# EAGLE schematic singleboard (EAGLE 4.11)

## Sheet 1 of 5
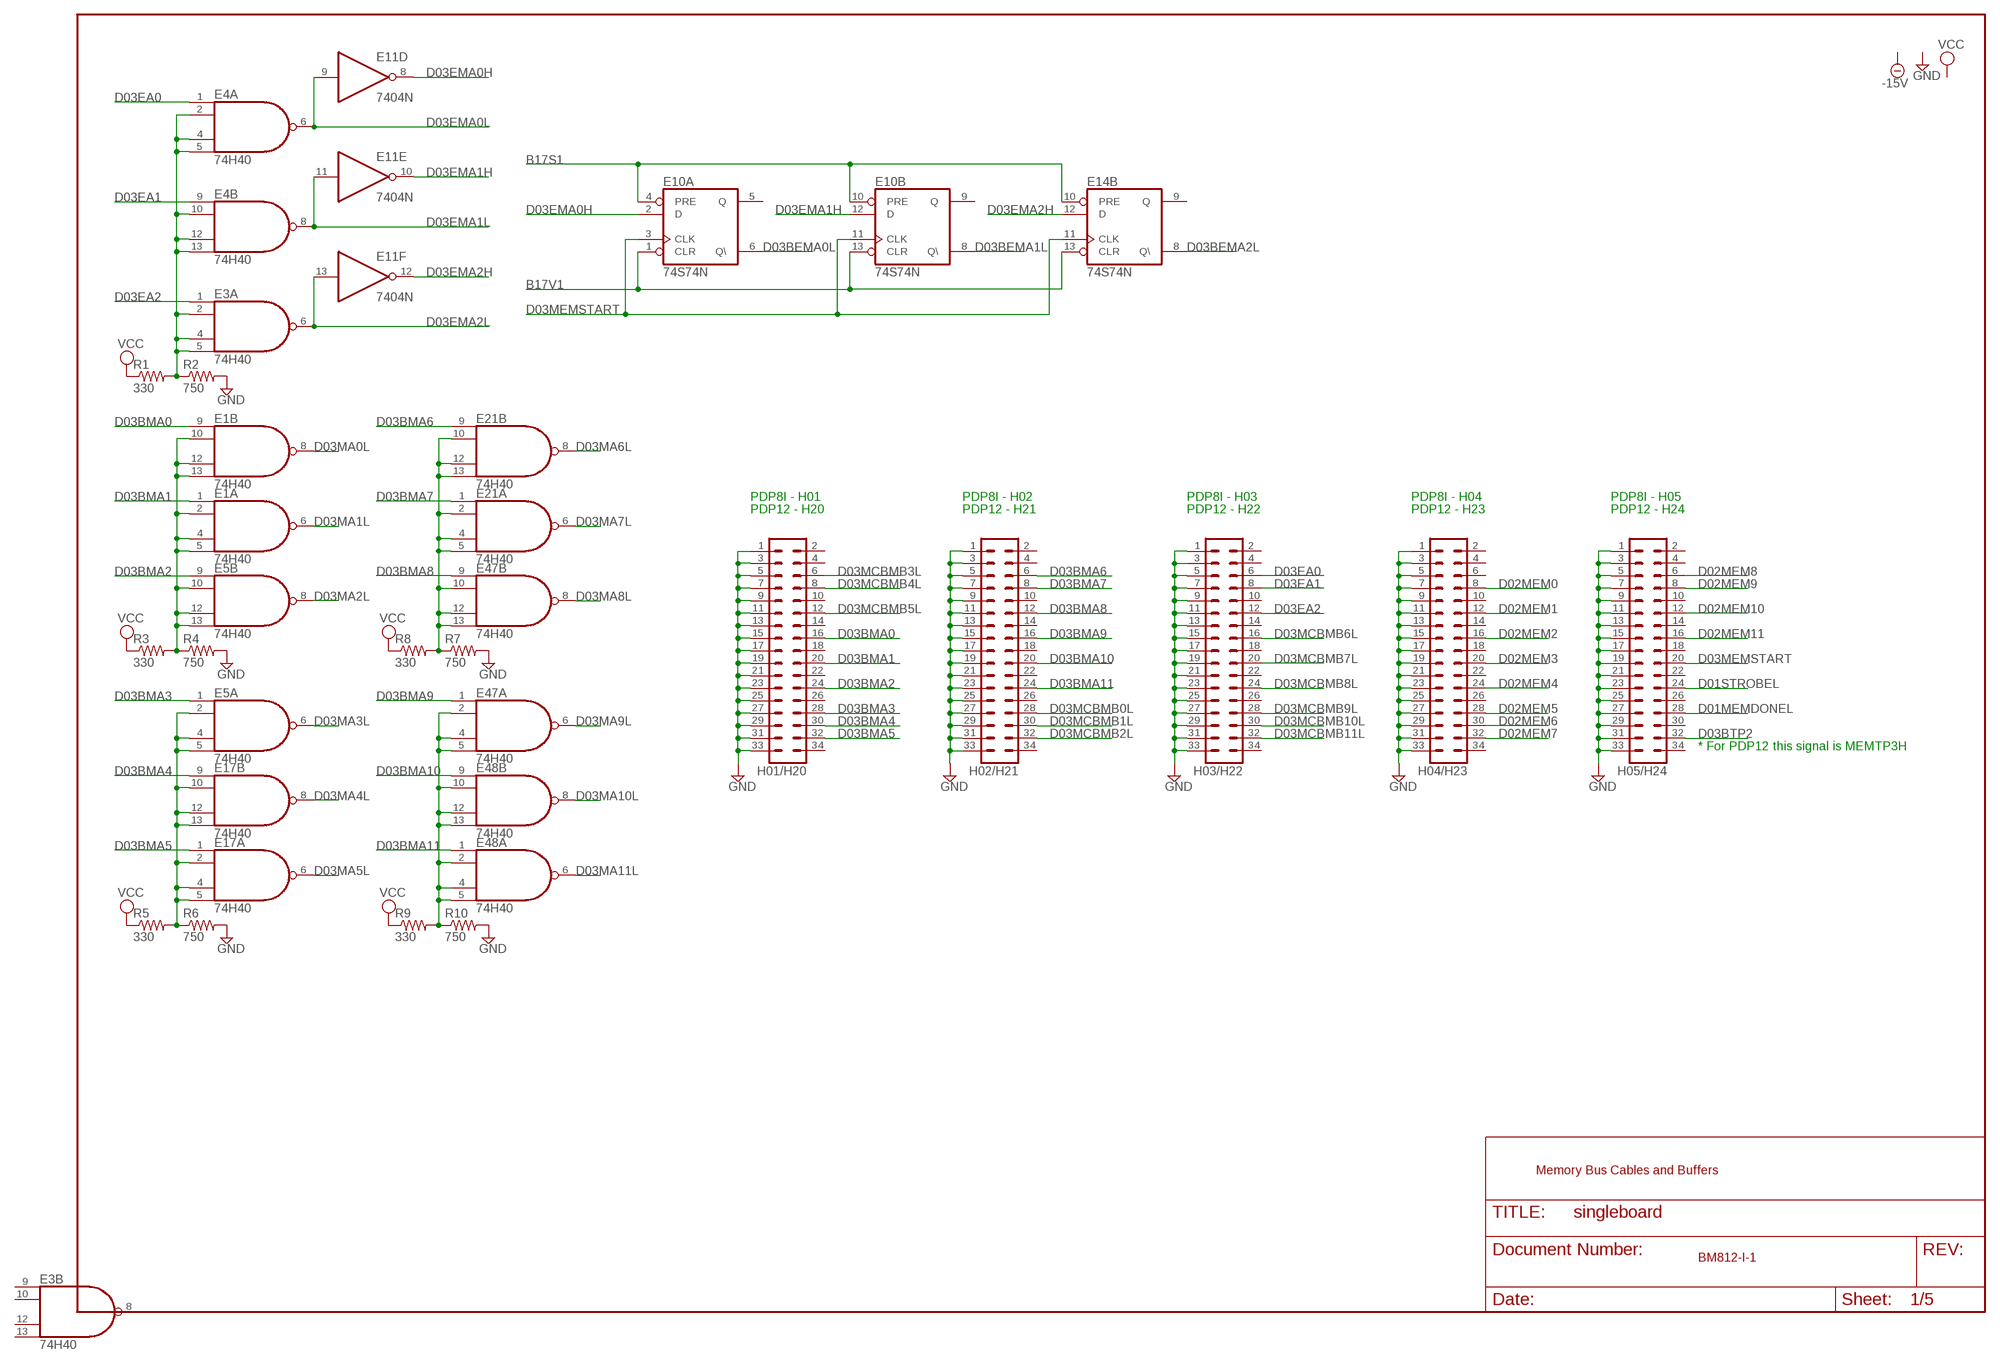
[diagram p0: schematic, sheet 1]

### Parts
E1  74H40  74S20N  [DIL14]
E3  74H40  74S20N  [DIL14]
E4  74H40  74S20N  [DIL14]
E5  74H40  74S20N  [DIL14]
E10  74S74N  [DIL14]
E11  7404N  [DIL14]
E14  74S74N  [DIL14]
E17  74H40  74S20N  [DIL14]
E21  74H40  74S20N  [DIL14]
E47  74H40  74S20N  [DIL14]
E48  74H40  74S20N  [DIL14]
H01/H20  MA17-2  [MA17-2]
H02/H21  MA17-2  [MA17-2]
H03/H22  MA17-2  [MA17-2]
H04/H23  MA17-2  [MA17-2]
H05/H24  MA17-2  [MA17-2]
R1  330  R-US_0207/10  [0207/10]
R2  750  R-US_0207/10  [0207/10]
R3  330  R-US_0207/10  [0207/10]
R4  750  R-US_0207/10  [0207/10]
R5  330  R-US_0207/10  [0207/10]
R6  750  R-US_0207/10  [0207/10]
R7  750  R-US_0207/10  [0207/10]
R8  330  R-US_0207/10  [0207/10]
R9  330  R-US_0207/10  [0207/10]
R10  750  R-US_0207/10  [0207/10]

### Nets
B17S1: E10.4(A:PRE) E10.10(B:PRE) E14.10(B:PRE) ; also sheet 3,4
B17V1: E10.1(A:CLR) E10.13(B:CLR) E14.13(B:CLR) ; also sheet 3,4
D01MEMDONEL: H05/H24.28 ; also sheet 4
D01STROBEL: H05/H24.24 ; also sheet 4
D02MEM0: H04/H23.8 ; also sheet 3
D02MEM1: H04/H23.12 ; also sheet 3
D02MEM2: H04/H23.16 ; also sheet 3
D02MEM3: H04/H23.20 ; also sheet 3
D02MEM4: H04/H23.24 ; also sheet 3
D02MEM5: H04/H23.28 ; also sheet 3
D02MEM6: H04/H23.30 ; also sheet 3
D02MEM7: H04/H23.32 ; also sheet 3
D02MEM8: H05/H24.6 ; also sheet 3
D02MEM9: H05/H24.8 ; also sheet 3
D02MEM10: H05/H24.12 ; also sheet 3
D02MEM11: H05/H24.16 ; also sheet 3
D03BEMA0L: E10.6(A:Q\) ; also sheet 5
D03BEMA1L: E10.8(B:Q\) ; also sheet 5
D03BEMA2L: E14.8(B:Q\) ; also sheet 5
D03BMA0: E1.9(B:I0) H01/H20.16
D03BMA1: E1.1(A:I0) H01/H20.20
D03BMA2: E5.9(B:I0) H01/H20.24
D03BMA3: E5.1(A:I0) H01/H20.28
D03BMA4: E17.9(B:I0) H01/H20.30
D03BMA5: E17.1(A:I0) H01/H20.32
D03BMA6: E21.9(B:I0) H02/H21.6
D03BMA7: E21.1(A:I0) H02/H21.8
D03BMA8: E47.9(B:I0) H02/H21.12
D03BMA9: E47.1(A:I0) H02/H21.16
D03BMA10: E48.9(B:I0) H02/H21.20
D03BMA11: E48.1(A:I0) H02/H21.24
D03BTP2: H05/H24.32 ; also sheet 4
D03EA0: E4.1(A:I0) H03/H22.6
D03EA1: E4.9(B:I0) H03/H22.8
D03EA2: E3.1(A:I0) H03/H22.12
D03EMA0H: E10.2(A:D) E11.8(D:O) ; also sheet 4
D03EMA0L: E4.6(A:O) E11.9(D:I) ; also sheet 4
D03EMA1H: E10.12(B:D) E11.10(E:O) ; also sheet 4
D03EMA1L: E4.8(B:O) E11.11(E:I) ; also sheet 4
D03EMA2H: E11.12(F:O) E14.12(B:D) ; also sheet 4
D03EMA2L: E3.6(A:O) E11.13(F:I) ; also sheet 4
D03MA0L: E1.8(B:O) ; also sheet 5
D03MA1L: E1.6(A:O) ; also sheet 5
D03MA2L: E5.8(B:O) ; also sheet 5
D03MA3L: E5.6(A:O) ; also sheet 5
D03MA4L: E17.8(B:O) ; also sheet 5
D03MA5L: E17.6(A:O) ; also sheet 5
D03MA6L: E21.8(B:O) ; also sheet 5
D03MA7L: E21.6(A:O) ; also sheet 5
D03MA8L: E47.8(B:O) ; also sheet 5
D03MA9L: E47.6(A:O) ; also sheet 5
D03MA10L: E48.8(B:O) ; also sheet 5
D03MA11L: E48.6(A:O) ; also sheet 5
D03MCBMB0L: H02/H21.28 ; also sheet 2
D03MCBMB1L: H02/H21.30 ; also sheet 2
D03MCBMB2L: H02/H21.32 ; also sheet 2
D03MCBMB3L: H01/H20.6 ; also sheet 2
D03MCBMB4L: H01/H20.8 ; also sheet 2
D03MCBMB5L: H01/H20.12 ; also sheet 2
D03MCBMB6L: H03/H22.16 ; also sheet 2
D03MCBMB7L: H03/H22.20 ; also sheet 2
D03MCBMB8L: H03/H22.24 ; also sheet 2
D03MCBMB9L: H03/H22.28 ; also sheet 2
D03MCBMB10L: H03/H22.30 ; also sheet 2
D03MCBMB11L: H03/H22.32 ; also sheet 2
D03MEMSTART: E10.3(A:CLK) E10.11(B:CLK) E14.11(B:CLK) H05/H24.20 ; also sheet 4
GND [Power]: H01/H20.1 H01/H20.3 H01/H20.5 H01/H20.7 H01/H20.9 H01/H20.11 H01/H20.13 H01/H20.15 H01/H20.17 H01/H20.19 H01/H20.21 H01/H20.23 H01/H20.25 H01/H20.27 H01/H20.29 H01/H20.31 H01/H20.33 H02/H21.1 H02/H21.3 H02/H21.5 H02/H21.7 H02/H21.9 H02/H21.11 H02/H21.13 H02/H21.15 H02/H21.17 H02/H21.19 H02/H21.21 H02/H21.23 H02/H21.25 H02/H21.27 H02/H21.29 H02/H21.31 H02/H21.33 H03/H22.1 H03/H22.3 H03/H22.5 H03/H22.7 H03/H22.9 H03/H22.11 H03/H22.13 H03/H22.15 H03/H22.17 H03/H22.19 H03/H22.21 H03/H22.23 H03/H22.25 H03/H22.27 H03/H22.29 H03/H22.31 H03/H22.33 H04/H23.1 H04/H23.3 H04/H23.5 H04/H23.7 H04/H23.9 H04/H23.11 H04/H23.13 H04/H23.15 H04/H23.17 H04/H23.19 H04/H23.21 H04/H23.23 H04/H23.25 H04/H23.27 H04/H23.29 H04/H23.31 H04/H23.33 H05/H24.1 H05/H24.3 H05/H24.5 H05/H24.7 H05/H24.9 H05/H24.11 H05/H24.13 H05/H24.15 H05/H24.17 H05/H24.19 H05/H24.21 H05/H24.23 H05/H24.25 H05/H24.27 H05/H24.29 H05/H24.31 H05/H24.33 R2.2 R4.2 R6.2 R7.2 R10.2 ; also sheet 2,4,5
N$1: E3.2(A:I1) E3.4(A:I2) E3.5(A:I3) E4.2(A:I1) E4.4(A:I2) E4.5(A:I3) E4.10(B:I1) E4.12(B:I2) E4.13(B:I3) R1.2 R2.1
N$2: E1.2(A:I1) E1.4(A:I2) E1.5(A:I3) E1.10(B:I1) E1.12(B:I2) E1.13(B:I3) E5.10(B:I1) E5.12(B:I2) E5.13(B:I3) R3.2 R4.1
N$4: E5.2(A:I1) E5.4(A:I2) E5.5(A:I3) E17.2(A:I1) E17.4(A:I2) E17.5(A:I3) E17.10(B:I1) E17.12(B:I2) E17.13(B:I3) R5.2 R6.1
N$6: E21.2(A:I1) E21.4(A:I2) E21.5(A:I3) E21.10(B:I1) E21.12(B:I2) E21.13(B:I3) E47.10(B:I1) E47.12(B:I2) E47.13(B:I3) R7.1 R8.2
N$36: E47.2(A:I1) E47.4(A:I2) E47.5(A:I3) E48.2(A:I1) E48.4(A:I2) E48.5(A:I3) E48.10(B:I1) E48.12(B:I2) E48.13(B:I3) R9.2 R10.1
VCC [Power]: R1.1 R3.1 R5.1 R8.1 R9.1 ; also sheet 2,4,5
Unconnected: E10.5(A:Q) E10.9(B:Q) H01/H20.2 H01/H20.4 H01/H20.10 H01/H20.14 H01/H20.18 H01/H20.22 H01/H20.26 H01/H20.34 H02/H21.2 H02/H21.4 H02/H21.10 H02/H21.14 H02/H21.18 H02/H21.22 H02/H21.26 H02/H21.34 H03/H22.2 H03/H22.4 H03/H22.10 H03/H22.14 H03/H22.18 H03/H22.22 H03/H22.26 H03/H22.34 H04/H23.2 H04/H23.4 H04/H23.6 H04/H23.10 H04/H23.14 H04/H23.18 H04/H23.22 H04/H23.26 H04/H23.34 H05/H24.2 H05/H24.4 H05/H24.10 H05/H24.14 H05/H24.18 H05/H24.22 H05/H24.26 H05/H24.30 H05/H24.34

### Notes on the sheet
- PDP8I - H01 | PDP8I - H02 | PDP8I - H03 | PDP8I - H04 | PDP8I - H05
- PDP12 - H20 | PDP12 - H21 | PDP12 - H22 | PDP12 - H23 | PDP12 - H24
- * For PDP12 this signal is MEMTP3H
- Memory Bus Cables and Buffers
- BM812-I-1

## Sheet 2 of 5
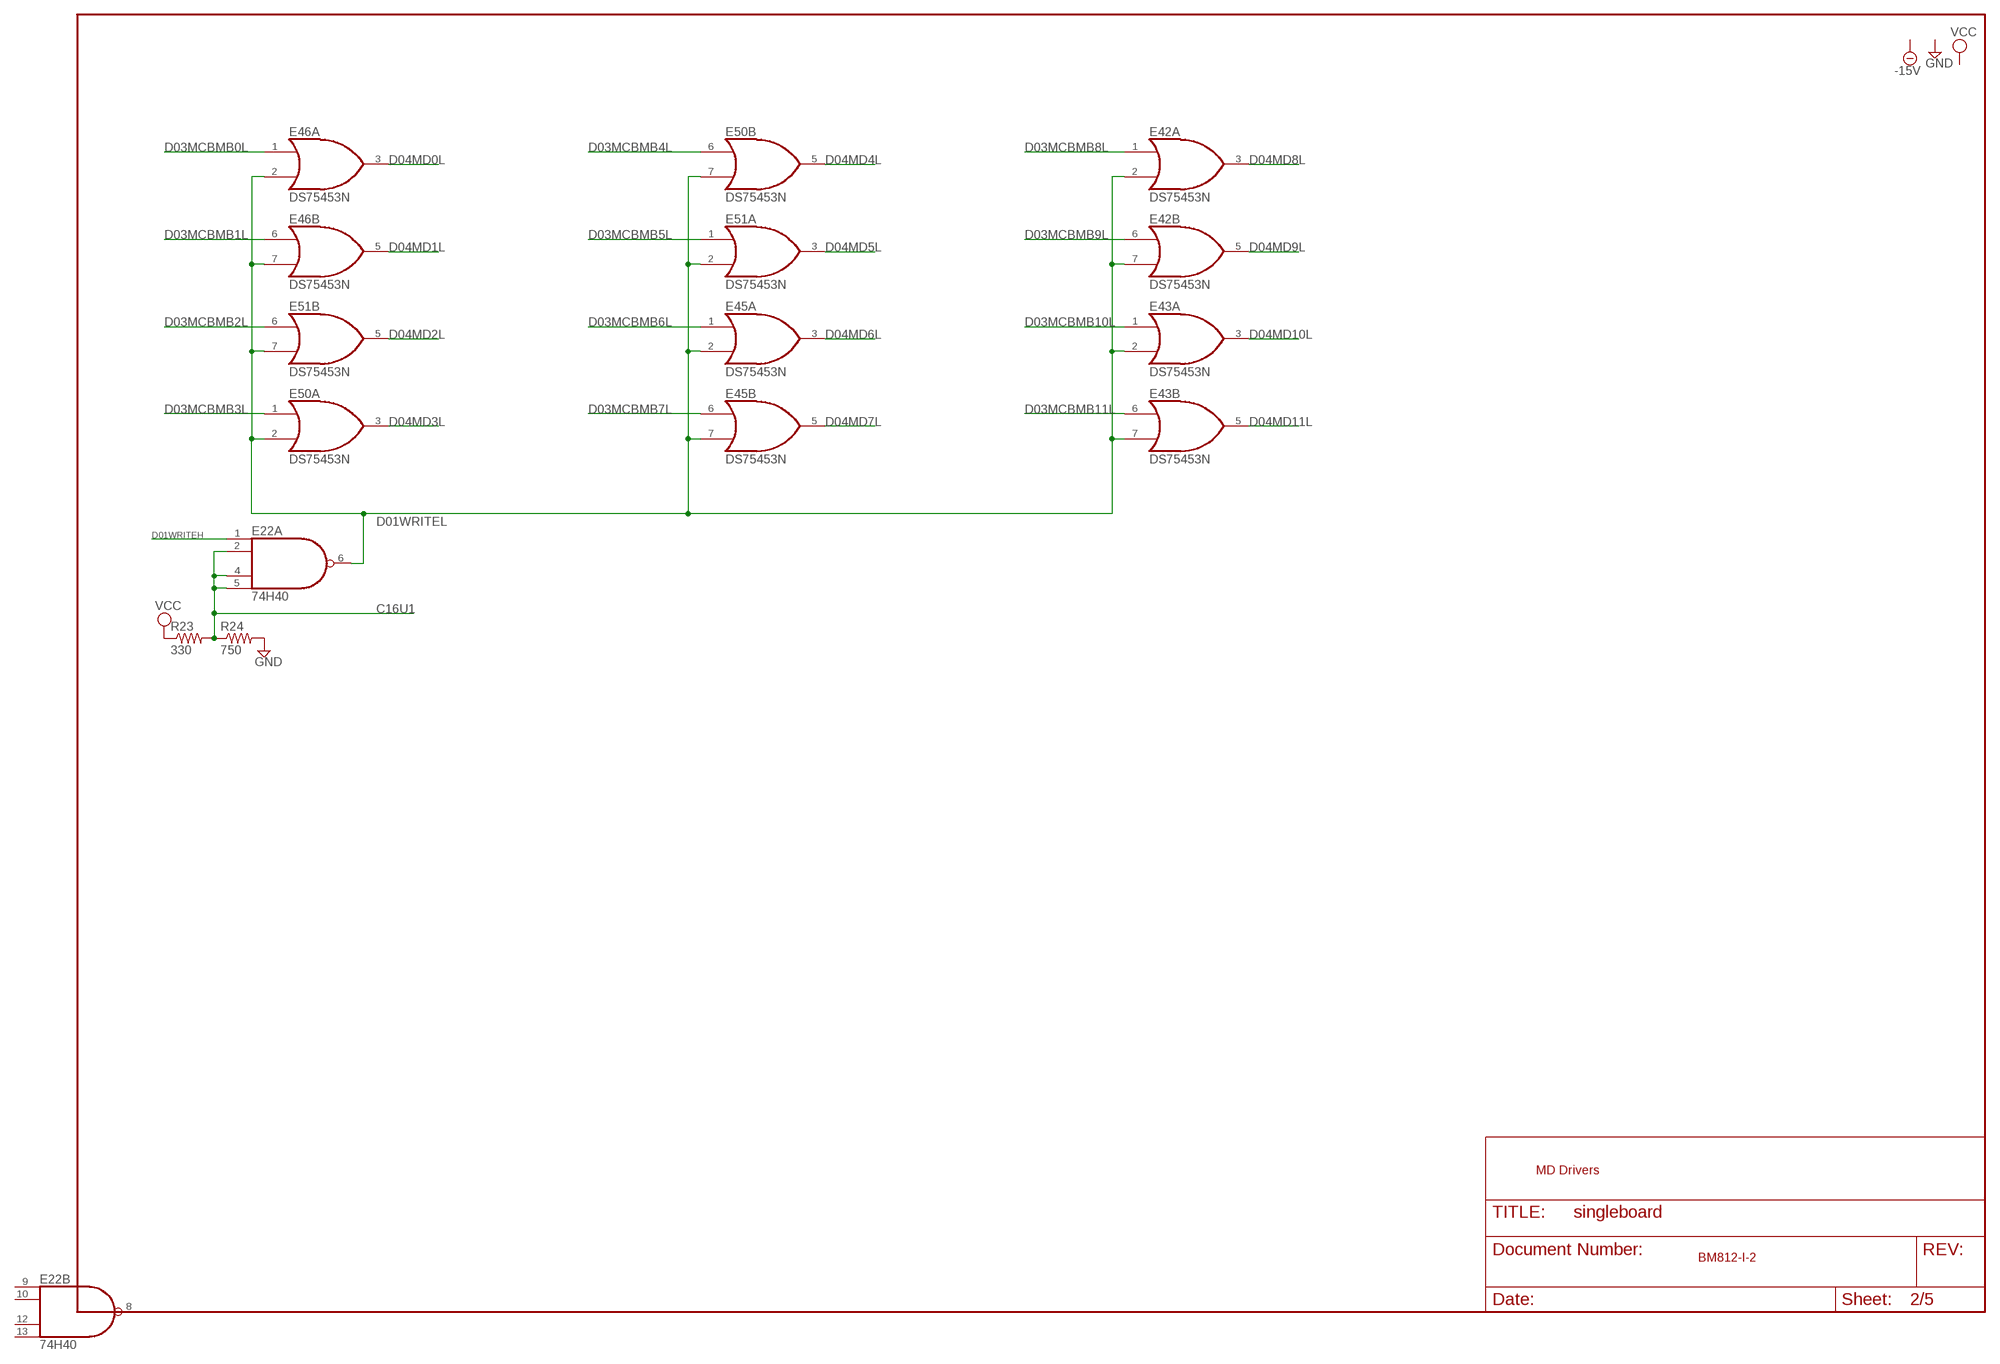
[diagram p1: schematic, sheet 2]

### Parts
E22  74H40  74S20N  [DIL14]
E42  DS75453N  [DIL08]
E43  DS75453N  [DIL08]
E45  DS75453N  [DIL08]
E46  DS75453N  [DIL08]
E50  DS75453N  [DIL08]
E51  DS75453N  [DIL08]
R23  330  R-US_0207/10  [0207/10]
R24  750  R-US_0207/10  [0207/10]

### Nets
C16U1: E22.2(A:I1) E22.4(A:I2) E22.5(A:I3) R23.2 R24.1 ; also sheet 3
D01WRITEH: E22.1(A:I0) ; also sheet 4
D01WRITEL: E22.6(A:O) E42.2(A:I1) E42.7(B:I1) E43.2(A:I1) E43.7(B:I1) E45.2(A:I1) E45.7(B:I1) E46.2(A:I1) E46.7(B:I1) E50.2(A:I1) E50.7(B:I1) E51.2(A:I1) E51.7(B:I1)
D03MCBMB0L: E46.1(A:I0) ; also sheet 1
D03MCBMB1L: E46.6(B:I0) ; also sheet 1
D03MCBMB2L: E51.6(B:I0) ; also sheet 1
D03MCBMB3L: E50.1(A:I0) ; also sheet 1
D03MCBMB4L: E50.6(B:I0) ; also sheet 1
D03MCBMB5L: E51.1(A:I0) ; also sheet 1
D03MCBMB6L: E45.1(A:I0) ; also sheet 1
D03MCBMB7L: E45.6(B:I0) ; also sheet 1
D03MCBMB8L: E42.1(A:I0) ; also sheet 1
D03MCBMB9L: E42.6(B:I0) ; also sheet 1
D03MCBMB10L: E43.1(A:I0) ; also sheet 1
D03MCBMB11L: E43.6(B:I0) ; also sheet 1
D04MD0L: E46.3(A:O) ; also sheet 3,5
D04MD1L: E46.5(B:O) ; also sheet 3,5
D04MD2L: E51.5(B:O) ; also sheet 3,5
D04MD3L: E50.3(A:O) ; also sheet 3,5
D04MD4L: E50.5(B:O) ; also sheet 3,5
D04MD5L: E51.3(A:O) ; also sheet 3,5
D04MD6L: E45.3(A:O) ; also sheet 3,5
D04MD7L: E45.5(B:O) ; also sheet 3,5
D04MD8L: E42.3(A:O) ; also sheet 3,5
D04MD9L: E42.5(B:O) ; also sheet 3,5
D04MD10L: E43.3(A:O) ; also sheet 3,5
D04MD11L: E43.5(B:O) ; also sheet 3,5
GND [Power]: R24.2 ; also sheet 1,4,5
VCC [Power]: R23.1 ; also sheet 1,4,5

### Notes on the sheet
- MD Drivers
- BM812-I-2

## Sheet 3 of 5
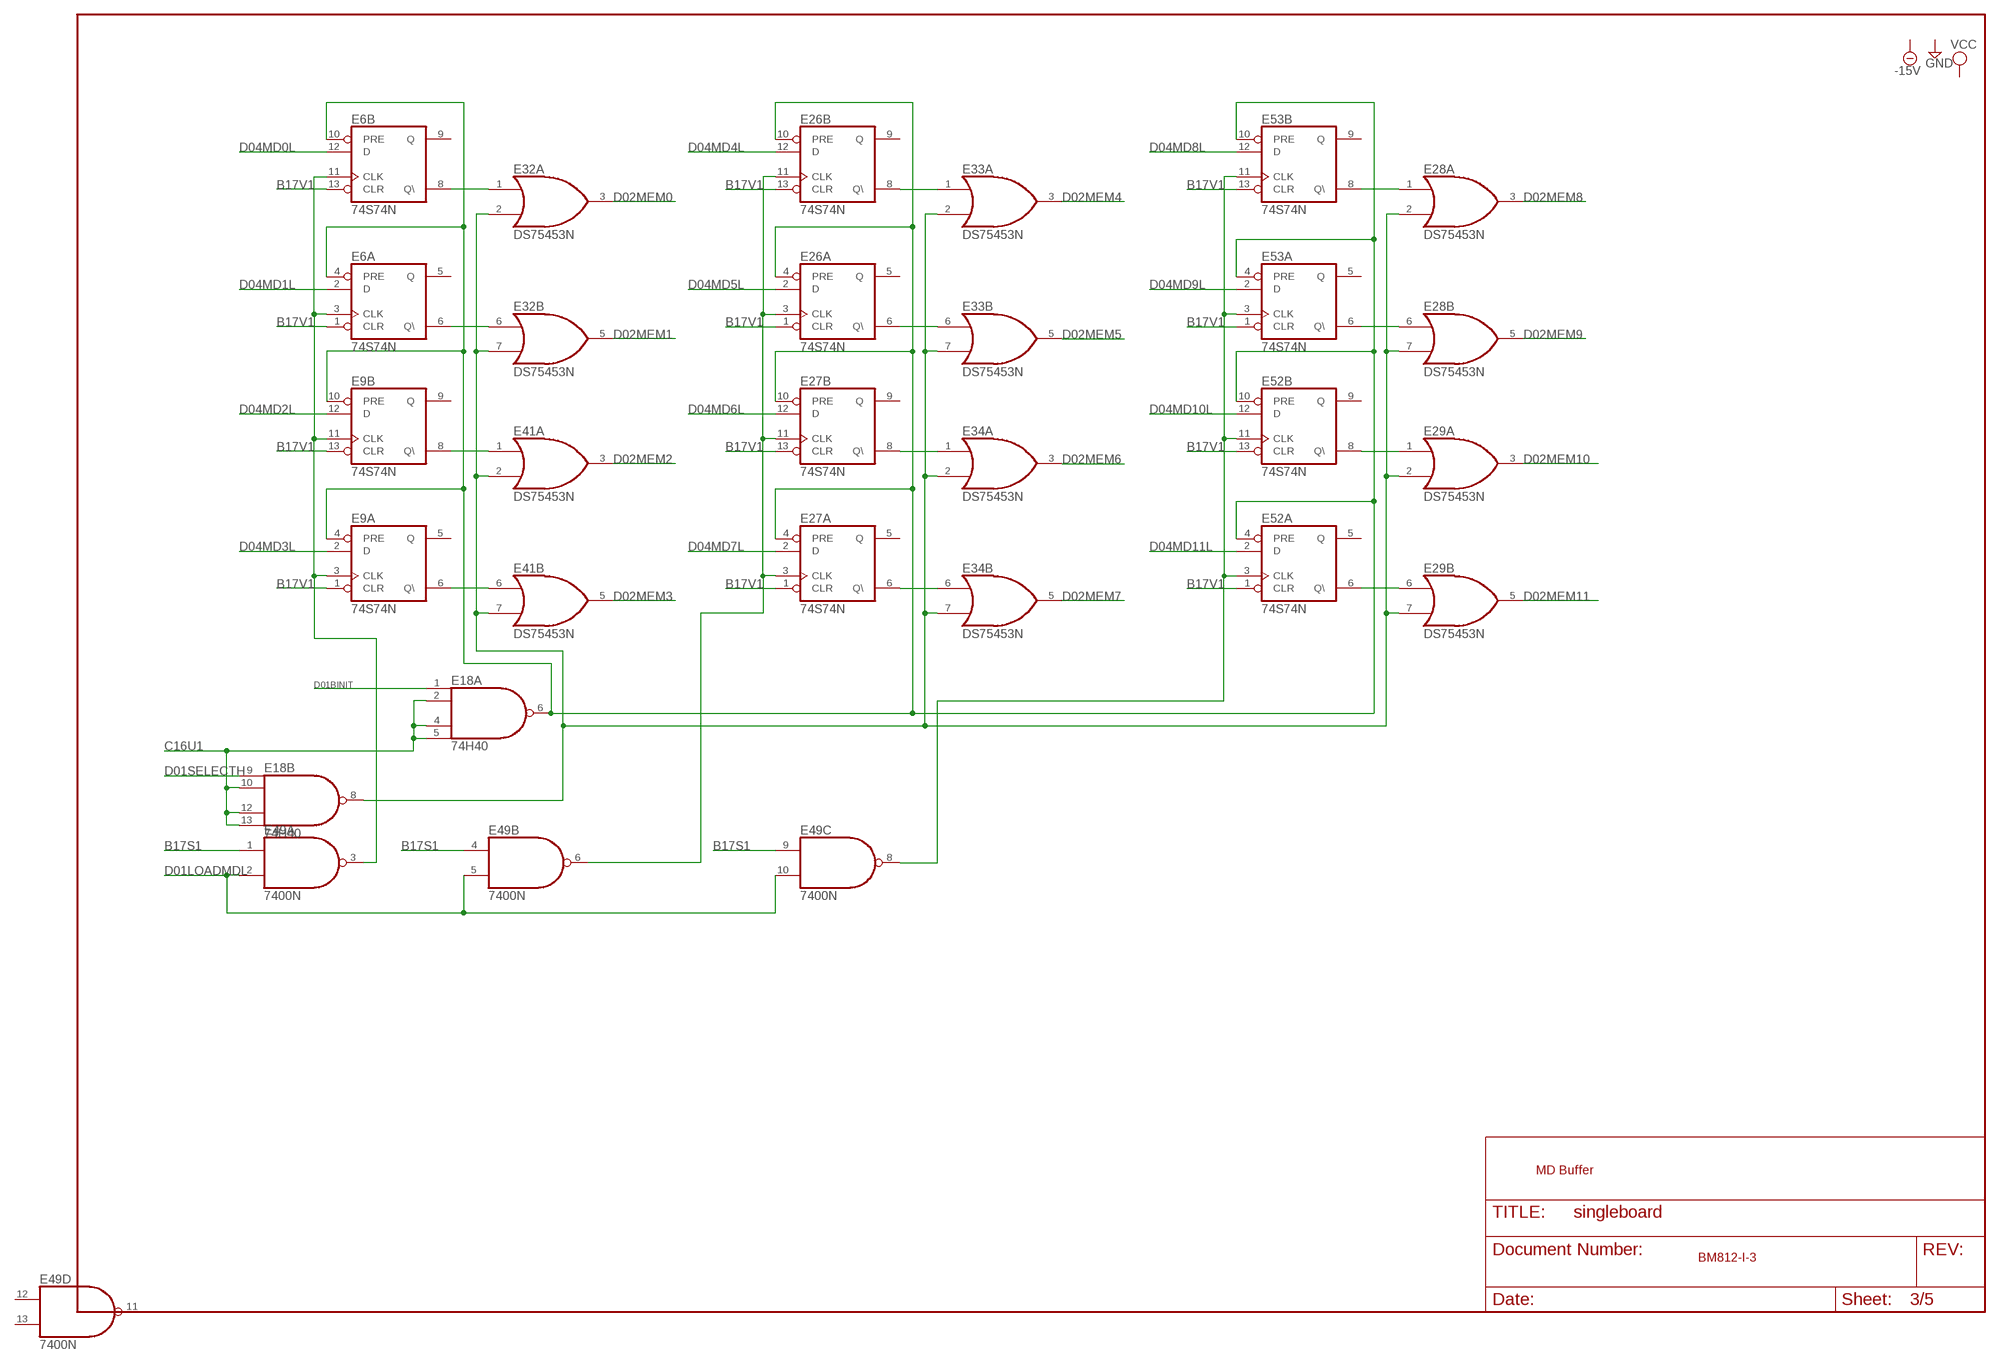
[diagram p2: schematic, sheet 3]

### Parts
E6  74S74N  [DIL14]
E9  74S74N  [DIL14]
E18  74H40  74S20N  [DIL14]
E26  74S74N  [DIL14]
E27  74S74N  [DIL14]
E28  DS75453N  [DIL08]
E29  DS75453N  [DIL08]
E32  DS75453N  [DIL08]
E33  DS75453N  [DIL08]
E34  DS75453N  [DIL08]
E41  DS75453N  [DIL08]
E49  7400N  [DIL14]
E52  74S74N  [DIL14]
E53  74S74N  [DIL14]

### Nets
B17S1: E49.1(A:I0) E49.4(B:I0) E49.9(C:I0) ; also sheet 1,4
B17V1: E6.1(A:CLR) E6.13(B:CLR) E9.1(A:CLR) E9.13(B:CLR) E26.1(A:CLR) E26.13(B:CLR) E27.1(A:CLR) E27.13(B:CLR) E52.1(A:CLR) E52.13(B:CLR) E53.1(A:CLR) E53.13(B:CLR) ; also sheet 1,4
C16U1: E18.2(A:I1) E18.4(A:I2) E18.5(A:I3) E18.10(B:I1) E18.12(B:I2) E18.13(B:I3) ; also sheet 2
D01BINIT: E18.1(A:I0) ; also sheet 4
D01LOADMDL: E49.2(A:I1) E49.5(B:I1) E49.10(C:I1) ; also sheet 4
D01SELECTH: E18.9(B:I0) ; also sheet 4
D02MEM0: E32.3(A:O) ; also sheet 1
D02MEM1: E32.5(B:O) ; also sheet 1
D02MEM2: E41.3(A:O) ; also sheet 1
D02MEM3: E41.5(B:O) ; also sheet 1
D02MEM4: E33.3(A:O) ; also sheet 1
D02MEM5: E33.5(B:O) ; also sheet 1
D02MEM6: E34.3(A:O) ; also sheet 1
D02MEM7: E34.5(B:O) ; also sheet 1
D02MEM8: E28.3(A:O) ; also sheet 1
D02MEM9: E28.5(B:O) ; also sheet 1
D02MEM10: E29.3(A:O) ; also sheet 1
D02MEM11: E29.5(B:O) ; also sheet 1
D04MD0L: E6.12(B:D) ; also sheet 2,5
D04MD1L: E6.2(A:D) ; also sheet 2,5
D04MD2L: E9.12(B:D) ; also sheet 2,5
D04MD3L: E9.2(A:D) ; also sheet 2,5
D04MD4L: E26.12(B:D) ; also sheet 2,5
D04MD5L: E26.2(A:D) ; also sheet 2,5
D04MD6L: E27.12(B:D) ; also sheet 2,5
D04MD7L: E27.2(A:D) ; also sheet 2,5
D04MD8L: E53.12(B:D) ; also sheet 2,5
D04MD9L: E53.2(A:D) ; also sheet 2,5
D04MD10L: E52.12(B:D) ; also sheet 2,5
D04MD11L: E52.2(A:D) ; also sheet 2,5
N$8: E6.3(A:CLK) E6.11(B:CLK) E9.3(A:CLK) E9.11(B:CLK) E49.3(A:O)
N$12: E9.6(A:Q\) E41.6(B:I0)
N$14: E6.8(B:Q\) E32.1(A:I0)
N$15: E6.6(A:Q\) E32.6(B:I0)
N$16: E26.3(A:CLK) E26.11(B:CLK) E27.3(A:CLK) E27.11(B:CLK) E49.6(B:O)
N$17: E9.8(B:Q\) E41.1(A:I0)
N$21: E6.4(A:PRE) E6.10(B:PRE) E9.4(A:PRE) E9.10(B:PRE) E18.6(A:O) E26.4(A:PRE) E26.10(B:PRE) E27.4(A:PRE) E27.10(B:PRE) E52.4(A:PRE) E52.10(B:PRE) E53.4(A:PRE) E53.10(B:PRE)
N$22: E18.8(B:O) E28.2(A:I1) E28.7(B:I1) E29.2(A:I1) E29.7(B:I1) E32.2(A:I1) E32.7(B:I1) E33.2(A:I1) E33.7(B:I1) E34.2(A:I1) E34.7(B:I1) E41.2(A:I1) E41.7(B:I1)
N$24: E26.6(A:Q\) E33.6(B:I0)
N$25: E27.6(A:Q\) E34.6(B:I0)
N$26: E27.8(B:Q\) E34.1(A:I0)
N$27: E26.8(B:Q\) E33.1(A:I0)
N$29: E29.6(B:I0) E52.6(A:Q\)
N$30: E29.1(A:I0) E52.8(B:Q\)
N$41: E49.8(C:O) E52.3(A:CLK) E52.11(B:CLK) E53.3(A:CLK) E53.11(B:CLK)
N$67: E28.6(B:I0) E53.6(A:Q\)
N$68: E28.1(A:I0) E53.8(B:Q\)
Unconnected: E6.5(A:Q) E6.9(B:Q) E9.5(A:Q) E9.9(B:Q) E26.5(A:Q) E26.9(B:Q) E27.5(A:Q) E27.9(B:Q) E52.5(A:Q) E52.9(B:Q) E53.5(A:Q) E53.9(B:Q)

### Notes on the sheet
- MD Buffer
- BM812-I-3

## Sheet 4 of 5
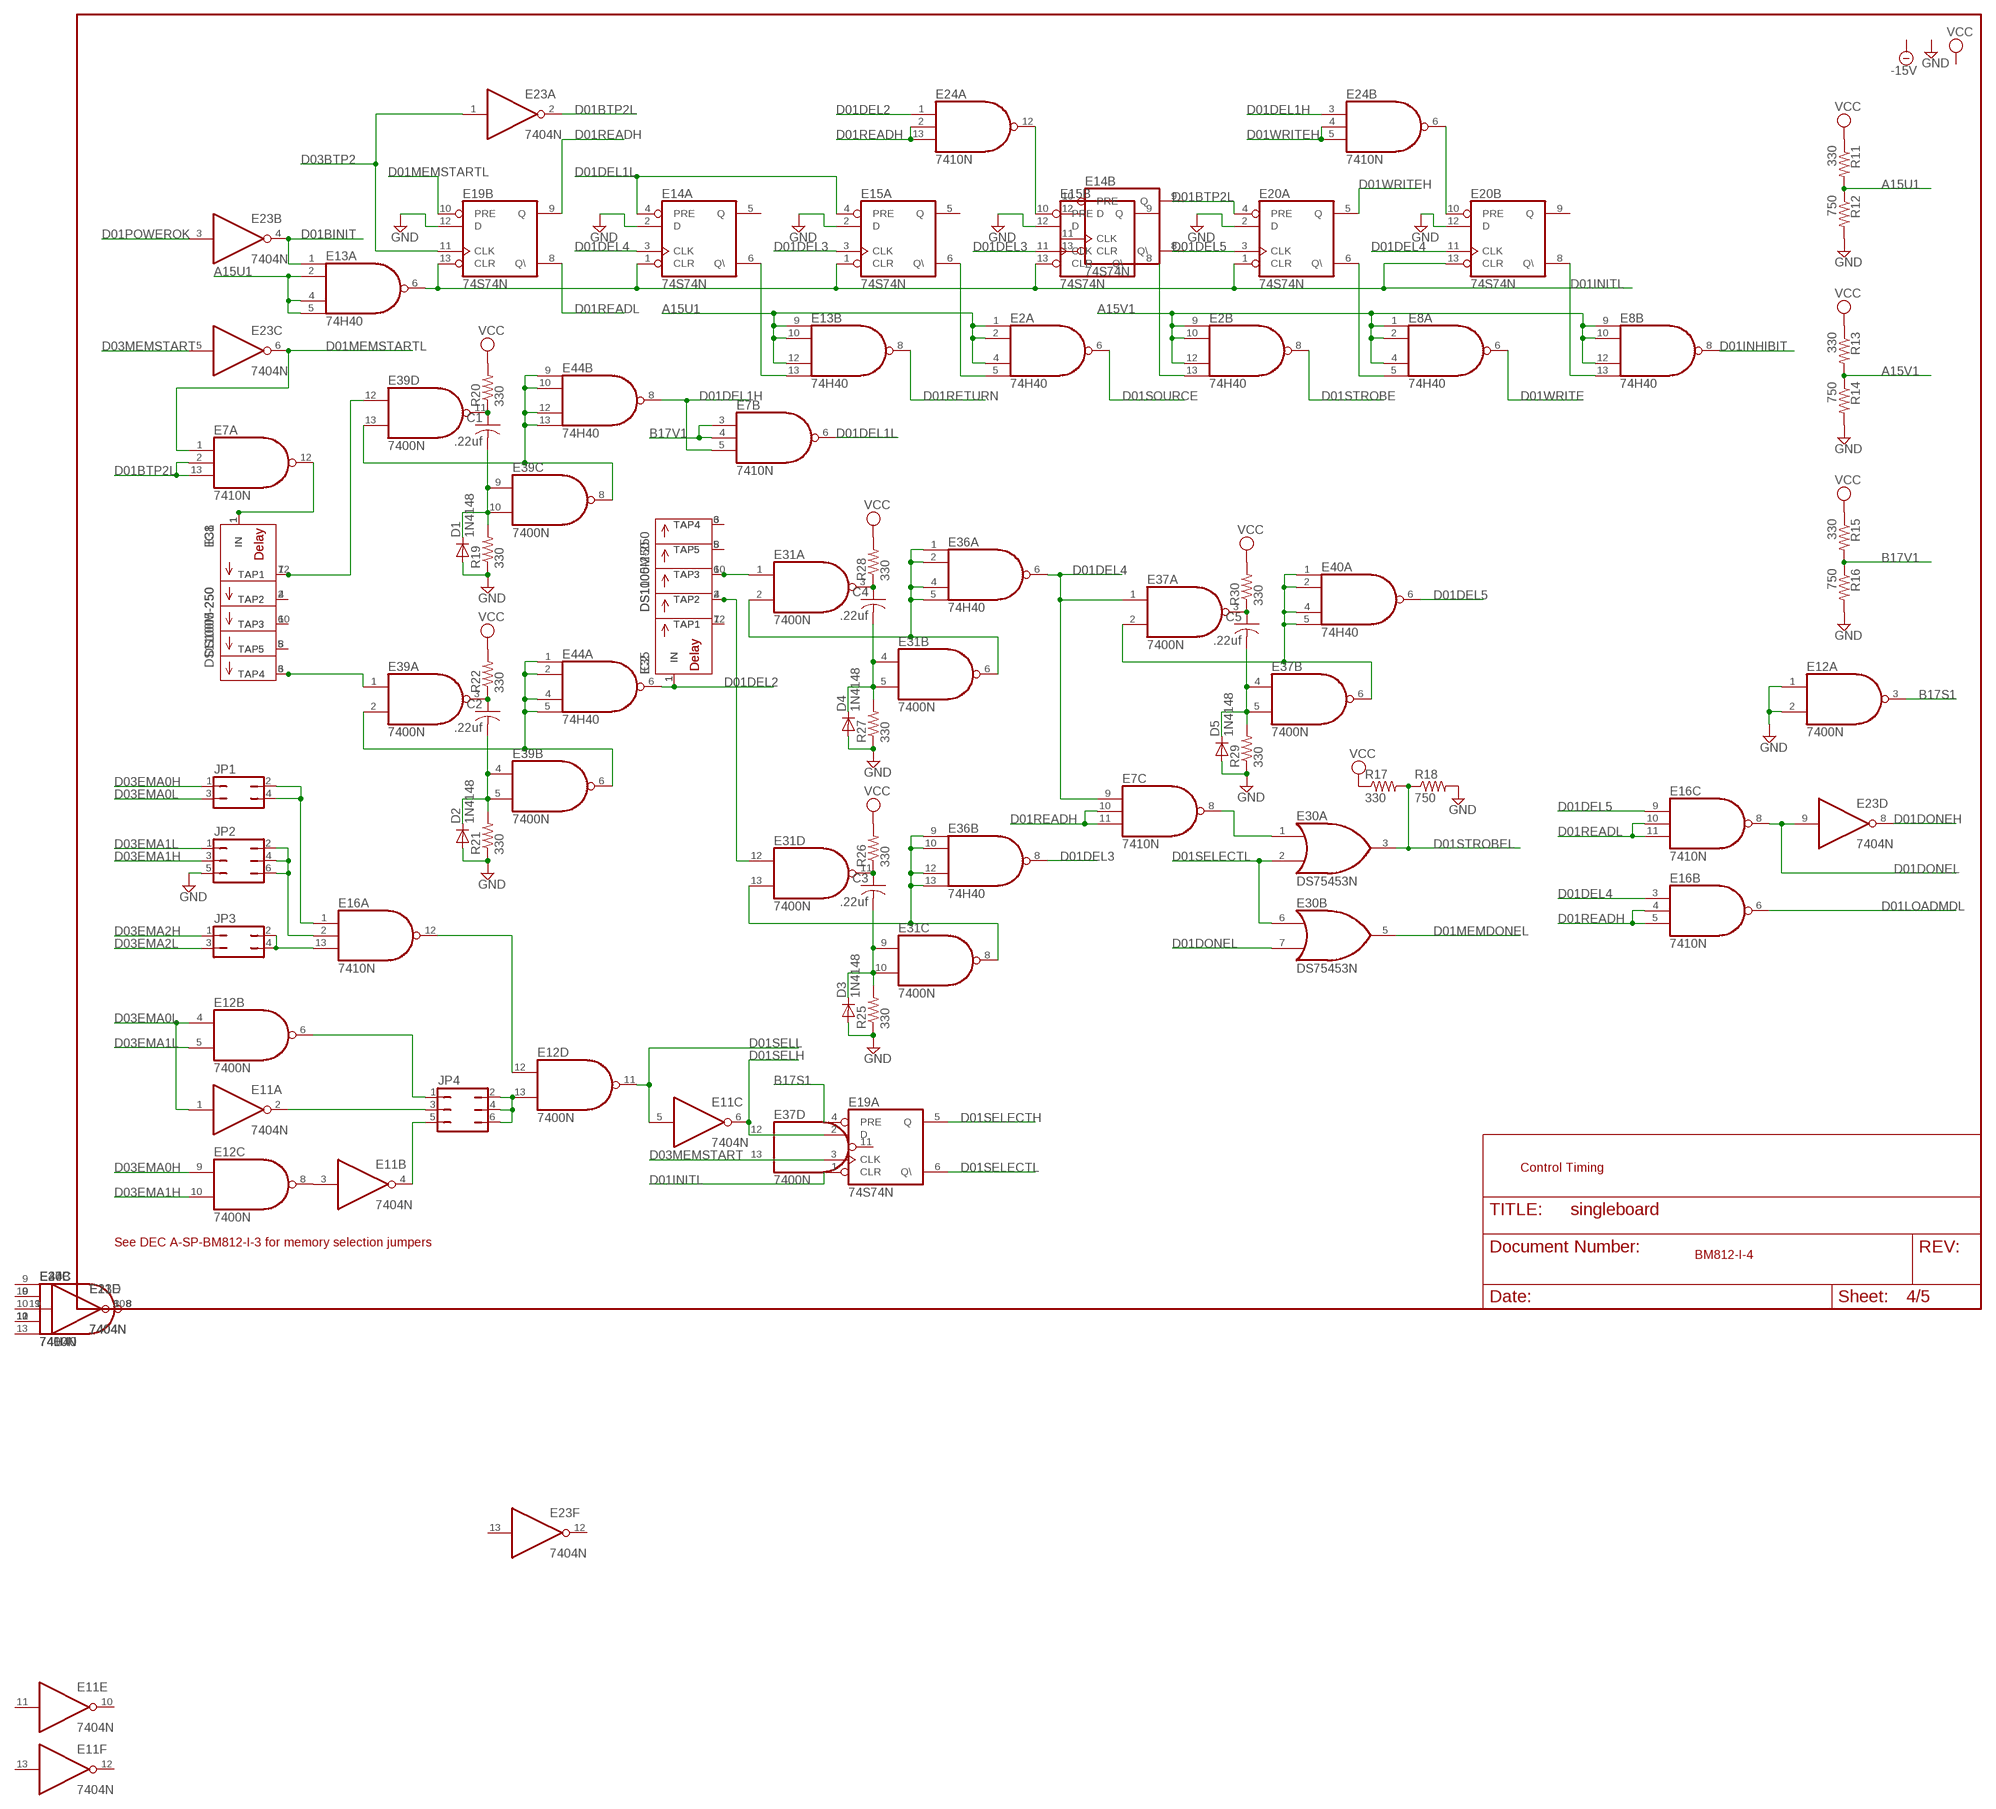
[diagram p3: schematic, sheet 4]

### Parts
C1  .22uf  C-US050-025X075  [C050-025X075]
C2  .22uf  C-US050-025X075  [C050-025X075]
C3  .22uf  C-US050-025X075  [C050-025X075]
C4  .22uf  C-US050-025X075  [C050-025X075]
C5  .22uf  C-US050-025X075  [C050-025X075]
D1  1N4148  [DO35-10]
D2  1N4148  [DO35-10]
D3  1N4148  [DO35-10]
D4  1N4148  [DO35-10]
D5  1N4148  [DO35-10]
E2  74H40  74S20N  [DIL14]
E7  7410N  [DIL14]
E8  74H40  74S20N  [DIL14]
E12  7400N  [DIL14]
E13  74H40  74S20N  [DIL14]
E15  74S74N  [DIL14]
E16  7410N  [DIL14]
E19  74S74N  [DIL14]
E20  74S74N  [DIL14]
E23  7404N  [DIL14]
E24  7410N  [DIL14]
E30  DS75453N  [DIL08]
E31  7400N  [DIL14]
E35  DS1005-250  MXD1000P  [DIL14]
E36  74H40  74S20N  [DIL14]
E37  7400N  [DIL14]
E38  DS1005-250  MXD1000P  [DIL14]
E39  7400N  [DIL14]
E40  74H40  74S20N  [DIL14]
E44  74H40  74S20N  [DIL14]
IC1  DS1100M-250  MXD1000  [DIL08]
IC2  DS1100M-250  MXD1000  [DIL08]
JP1  JP2Q  [JP2Q]
JP2  JP3Q  [JP3Q]
JP3  JP2Q  [JP2Q]
JP4  JP3Q  [JP3Q]
R11  330  R-US_0207/10  [0207/10]
R12  750  R-US_0207/10  [0207/10]
R13  330  R-US_0207/10  [0207/10]
R14  750  R-US_0207/10  [0207/10]
R15  330  R-US_0207/10  [0207/10]
R16  750  R-US_0207/10  [0207/10]
R17  330  R-US_0207/10  [0207/10]
R18  750  R-US_0207/10  [0207/10]
R19  330  R-US_0207/10  [0207/10]
R20  330  R-US_0207/10  [0207/10]
R21  330  R-US_0207/10  [0207/10]
R22  330  R-US_0207/10  [0207/10]
R25  330  R-US_0207/10  [0207/10]
R26  330  R-US_0207/10  [0207/10]
R27  330  R-US_0207/10  [0207/10]
R28  330  R-US_0207/10  [0207/10]
R29  330  R-US_0207/10  [0207/10]
R30  330  R-US_0207/10  [0207/10]

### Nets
A15U1: E2.1(A:I0) E2.2(A:I1) E2.4(A:I2) E13.2(A:I1) E13.4(A:I2) E13.5(A:I3) E13.9(B:I0) E13.10(B:I1) E13.12(B:I2) R11.2 R12.1 ; also sheet 5
A15V1: E2.9(B:I0) E2.10(B:I1) E2.12(B:I2) E8.1(A:I0) E8.2(A:I1) E8.4(A:I2) E8.9(B:I0) E8.10(B:I1) E8.12(B:I2) R13.2 R14.1
B17S1: E12.3(A:O) E19.4(A:PRE) ; also sheet 1,3
B17V1: E7.3(B:I0) E7.4(B:I1) R15.2 R16.1 ; also sheet 1,3
D01BINIT: E13.1(A:I0) E23.4(B:O) ; also sheet 3
D01BTP2L: E7.2(A:I1) E7.13(A:I2) E20.4(A:PRE) E23.2(A:O)
D01DEL1H: E7.5(B:I2) E24.3(B:I0) E44.8(B:O)
D01DEL1L: E7.6(B:O) E14.4(A:PRE) E15.4(A:PRE)
D01DEL2: E24.1(A:I0) E35.1(IN) E44.6(A:O) IC2.1(IN)
D01DEL3: E15.3(A:CLK) E15.11(B:CLK) E36.8(B:O)
D01DEL4: E7.9(C:I0) E14.3(A:CLK) E16.3(B:I0) E20.11(B:CLK) E36.6(A:O) E37.1(A:I0)
D01DEL5: E16.9(C:I0) E20.3(A:CLK) E40.6(A:O)
D01DONEH: E23.8(D:O) ; also sheet 5
D01DONEL: E16.8(C:O) E23.9(D:I) E30.7(B:I1)
D01INHIBIT: E8.8(B:O) ; also sheet 5
D01INITL: E13.6(A:O) E14.1(A:CLR) E15.1(A:CLR) E15.13(B:CLR) E19.1(A:CLR) E19.13(B:CLR) E20.1(A:CLR) E20.13(B:CLR)
D01LOADMDL: E16.6(B:O) ; also sheet 3
D01MEMDONEL: E30.5(B:O) ; also sheet 1
D01MEMSTARTL: E7.1(A:I0) E19.10(B:PRE) E23.6(C:O)
D01POWEROK: E23.3(B:I) ; also sheet 5
D01READH: E7.10(C:I1) E7.11(C:I2) E16.4(B:I1) E16.5(B:I2) E19.9(B:Q) E24.2(A:I1) E24.13(A:I2)
D01READL: E16.10(C:I1) E16.11(C:I2) E19.8(B:Q\) ; also sheet 5
D01RETURN: E13.8(B:O) ; also sheet 5
D01SELECTH: E19.5(A:Q) ; also sheet 3
D01SELECTL: E19.6(A:Q\) E30.2(A:I1) E30.6(B:I0)
D01SELH: E11.6(C:O) E19.2(A:D)
D01SELL: E11.5(C:I) E12.11(D:O)
D01SOURCE: E2.6(A:O) ; also sheet 5
D01STROBE: E2.8(B:O) ; also sheet 5
D01STROBEL: E30.3(A:O) R17.2 R18.1 ; also sheet 1
D01WRITE: E8.6(A:O) ; also sheet 5
D01WRITEH: E20.5(A:Q) E24.4(B:I1) E24.5(B:I2) ; also sheet 2
D03BTP2: E19.11(B:CLK) E23.1(A:I) ; also sheet 1
D03EMA0H: E12.9(C:I0) JP1.1 ; also sheet 1
D03EMA0L: E11.1(A:I) E12.4(B:I0) JP1.3 ; also sheet 1
D03EMA1H: E12.10(C:I1) JP2.3 ; also sheet 1
D03EMA1L: E12.5(B:I1) JP2.1 ; also sheet 1
D03EMA2H: JP3.1 ; also sheet 1
D03EMA2L: JP3.3 ; also sheet 1
D03MEMSTART: E19.3(A:CLK) E23.5(C:I) ; also sheet 1
GND [Power]: D1.A D2.A D3.A D4.A D5.A E12.1(A:I0) E12.2(A:I1) E14.2(A:D) E15.2(A:D) E15.12(B:D) E19.12(B:D) E20.2(A:D) E20.12(B:D) JP2.5 R12.2 R14.2 R16.2 R18.2 R19.1 R21.1 R25.1 R27.1 R29.1 ; also sheet 1,2,5
N$3: C3.2 D3.C E31.9(C:I0) E31.10(C:I1) R25.2
N$5: C5.2 D5.C E37.4(B:I0) E37.5(B:I1) R29.2
N$7: E12.13(D:I1) JP4.2 JP4.4 JP4.6
N$9: C2.2 D2.C E39.4(B:I0) E39.5(B:I1) R21.2
N$10: E38.12(TAP1) E39.12(D:I0) IC1.7(TAP1)
N$11: E31.12(D:I0) E35.4(TAP2) IC2.2(TAP2)
N$13: C1.2 D1.C E39.9(C:I0) E39.10(C:I1) R19.2
N$18: E39.8(C:O) E39.13(D:I1) E44.9(B:I0) E44.10(B:I1) E44.12(B:I2) E44.13(B:I3)
N$19: C1.1 E39.11(D:O) R20.1
N$20: C2.1 E39.3(A:O) R22.1
N$23: E39.2(A:I1) E39.6(B:O) E44.1(A:I0) E44.2(A:I1) E44.4(A:I2) E44.5(A:I3)
N$28: C3.1 E31.11(D:O) R26.1
N$31: E38.6(TAP4) E39.1(A:I0) IC1.3(TAP4)
N$32: E31.8(C:O) E31.13(D:I1) E36.9(B:I0) E36.10(B:I1) E36.12(B:I2) E36.13(B:I3)
N$33: C4.2 D4.C E31.4(B:I0) E31.5(B:I1) R27.2
N$34: C4.1 E31.3(A:O) R28.1
N$35: E7.12(A:O) E38.1(IN) IC1.1(IN)
N$37: E31.2(A:I1) E31.6(B:O) E36.1(A:I0) E36.2(A:I1) E36.4(A:I2) E36.5(A:I3)
N$38: E31.1(A:I0) E35.10(TAP3) IC2.6(TAP3)
N$39: C5.1 E37.3(A:O) R30.1
N$40: E37.2(A:I1) E37.6(B:O) E40.1(A:I0) E40.2(A:I1) E40.4(A:I2) E40.5(A:I3)
N$46: E15.10(B:PRE) E24.12(A:O)
N$48: E35.12(TAP1) IC2.7(TAP1)
N$49: E35.6(TAP4) IC2.3(TAP4)
N$50: E35.8(TAP5) IC2.5(TAP5)
N$51: E38.4(TAP2) IC1.2(TAP2)
N$52: E38.10(TAP3) IC1.6(TAP3)
N$53: E38.8(TAP5) IC1.5(TAP5)
N$73: E12.6(B:O) JP4.1
N$92: E20.10(B:PRE) E24.6(B:O)
N$94: E7.8(C:O) E30.1(A:I0)
N$96: E13.13(B:I3) E14.6(A:Q\)
N$100: E2.5(A:I3) E15.6(A:Q\)
N$101: E2.13(B:I3) E15.8(B:Q\)
N$103: E11.2(A:O) JP4.3
N$104: E8.5(A:I3) E20.6(A:Q\)
N$108: E11.3(B:I) E12.8(C:O)
N$109: E8.13(B:I3) E20.8(B:Q\)
N$111: E11.4(B:O) JP4.5
N$113: E16.13(A:I2) JP3.2 JP3.4
N$128: E16.2(A:I1) JP2.2 JP2.4 JP2.6
N$129: E16.1(A:I0) JP1.2 JP1.4
N$132: E12.12(D:I0) E16.12(A:O)
VCC [Power]: R11.1 R13.1 R15.1 R17.1 R20.2 R22.2 R26.2 R28.2 R30.2 ; also sheet 1,2,5
Unconnected: E14.5(A:Q) E14.9(B:Q) E15.5(A:Q) E15.9(B:Q) E20.9(B:Q) E35.2(NC) E35.3(NC) E35.5(NC) E35.9(NC) E35.11(NC) E35.13(NC) E38.2(NC) E38.3(NC) E38.5(NC) E38.9(NC) E38.11(NC) E38.13(NC)

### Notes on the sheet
- Control Timing
- See DEC A-SP-BM812-I-3 for memory selection jumpers
- BM812-I-4

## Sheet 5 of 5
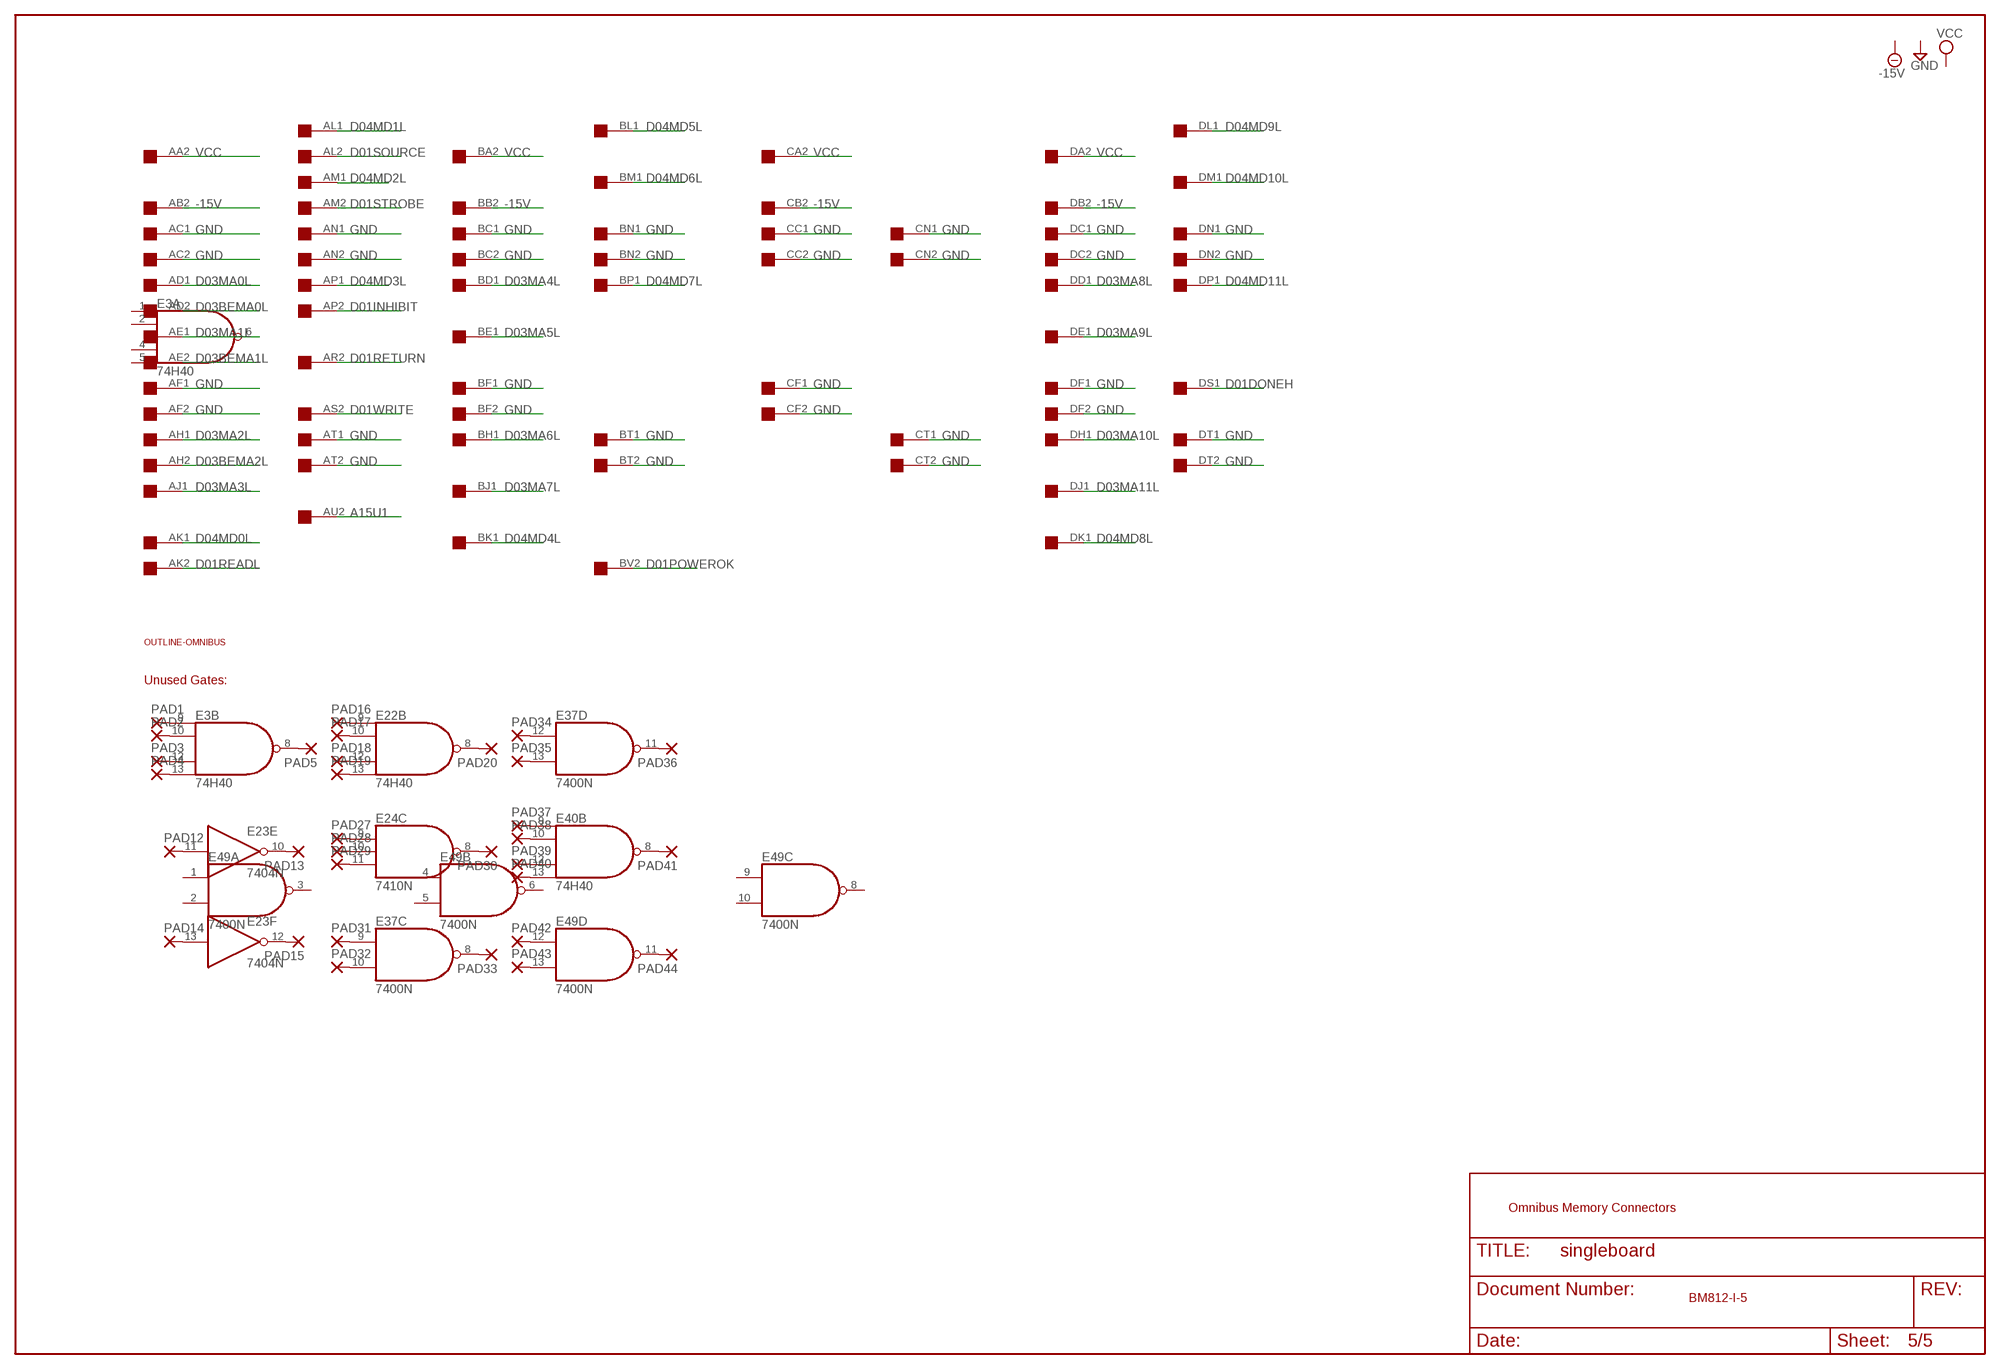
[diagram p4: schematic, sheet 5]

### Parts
PAD1  1,6/0,8  [1,6/0,8]
PAD2  1,6/0,8  [1,6/0,8]
PAD3  1,6/0,8  [1,6/0,8]
PAD4  1,6/0,8  [1,6/0,8]
PAD5  1,6/0,8  [1,6/0,8]
PAD12  1,6/0,8  [1,6/0,8]
PAD13  1,6/0,8  [1,6/0,8]
PAD14  1,6/0,8  [1,6/0,8]
PAD15  1,6/0,8  [1,6/0,8]
PAD16  1,6/0,8  [1,6/0,8]
PAD17  1,6/0,8  [1,6/0,8]
PAD18  1,6/0,8  [1,6/0,8]
PAD19  1,6/0,8  [1,6/0,8]
PAD20  1,6/0,8  [1,6/0,8]
PAD27  1,6/0,8  [1,6/0,8]
PAD28  1,6/0,8  [1,6/0,8]
PAD29  1,6/0,8  [1,6/0,8]
PAD30  1,6/0,8  [1,6/0,8]
PAD31  1,6/0,8  [1,6/0,8]
PAD32  1,6/0,8  [1,6/0,8]
PAD33  1,6/0,8  [1,6/0,8]
PAD34  1,6/0,8  [1,6/0,8]
PAD35  1,6/0,8  [1,6/0,8]
PAD36  1,6/0,8  [1,6/0,8]
PAD37  1,6/0,8  [1,6/0,8]
PAD38  1,6/0,8  [1,6/0,8]
PAD39  1,6/0,8  [1,6/0,8]
PAD40  1,6/0,8  [1,6/0,8]
PAD41  1,6/0,8  [1,6/0,8]
PAD42  1,6/0,8  [1,6/0,8]
PAD43  1,6/0,8  [1,6/0,8]
PAD44  1,6/0,8  [1,6/0,8]
U$1  QUAD  [EDGE-CON8]
U$2  OUTLINE-OMNIBUS  [OMNIBUS]

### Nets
-15V [Power]: U$1.AB2 U$1.BB2 U$1.CB2 U$1.DB2
A15U1: U$1.AU2 ; also sheet 4
D01DONEH: U$1.DS1 ; also sheet 4
D01INHIBIT: U$1.AP2 ; also sheet 4
D01POWEROK: U$1.BV2 ; also sheet 4
D01READL: U$1.AK2 ; also sheet 4
D01RETURN: U$1.AR2 ; also sheet 4
D01SOURCE: U$1.AL2 ; also sheet 4
D01STROBE: U$1.AM2 ; also sheet 4
D01WRITE: U$1.AS2 ; also sheet 4
D03BEMA0L: U$1.AD2 ; also sheet 1
D03BEMA1L: U$1.AE2 ; also sheet 1
D03BEMA2L: U$1.AH2 ; also sheet 1
D03MA0L: U$1.AD1 ; also sheet 1
D03MA1L: U$1.AE1 ; also sheet 1
D03MA2L: U$1.AH1 ; also sheet 1
D03MA3L: U$1.AJ1 ; also sheet 1
D03MA4L: U$1.BD1 ; also sheet 1
D03MA5L: U$1.BE1 ; also sheet 1
D03MA6L: U$1.BH1 ; also sheet 1
D03MA7L: U$1.BJ1 ; also sheet 1
D03MA8L: U$1.DD1 ; also sheet 1
D03MA9L: U$1.DE1 ; also sheet 1
D03MA10L: U$1.DH1 ; also sheet 1
D03MA11L: U$1.DJ1 ; also sheet 1
D04MD0L: U$1.AK1 ; also sheet 2,3
D04MD1L: U$1.AL1 ; also sheet 2,3
D04MD2L: U$1.AM1 ; also sheet 2,3
D04MD3L: U$1.AP1 ; also sheet 2,3
D04MD4L: U$1.BK1 ; also sheet 2,3
D04MD5L: U$1.BL1 ; also sheet 2,3
D04MD6L: U$1.BM1 ; also sheet 2,3
D04MD7L: U$1.BP1 ; also sheet 2,3
D04MD8L: U$1.DK1 ; also sheet 2,3
D04MD9L: U$1.DL1 ; also sheet 2,3
D04MD10L: U$1.DM1 ; also sheet 2,3
D04MD11L: U$1.DP1 ; also sheet 2,3
GND [Power]: U$1.AC1 U$1.AC2 U$1.AF1 U$1.AF2 U$1.AN1 U$1.AN2 U$1.AT1 U$1.AT2 U$1.BC1 U$1.BC2 U$1.BF1 U$1.BF2 U$1.BN1 U$1.BN2 U$1.BT1 U$1.BT2 U$1.CC1 U$1.CC2 U$1.CF1 U$1.CF2 U$1.CN1 U$1.CN2 U$1.CT1 U$1.CT2 U$1.DC1 U$1.DC2 U$1.DF1 U$1.DF2 U$1.DN1 U$1.DN2 U$1.DT1 U$1.DT2 ; also sheet 1,2,4
N$42: E3.9(B:I0) PAD1.1(P)
N$43: E3.10(B:I1) PAD2.1(P)
N$44: E3.12(B:I2) PAD3.1(P)
N$45: E3.13(B:I3) PAD4.1(P)
N$47: E3.8(B:O) PAD5.1(P)
N$54: E23.11(E:I) PAD12.1(P)
N$55: E23.10(E:O) PAD13.1(P)
N$56: E23.13(F:I) PAD14.1(P)
N$57: E23.12(F:O) PAD15.1(P)
N$58: E22.9(B:I0) PAD16.1(P)
N$59: E22.10(B:I1) PAD17.1(P)
N$60: E22.12(B:I2) PAD18.1(P)
N$61: E22.13(B:I3) PAD19.1(P)
N$62: E22.8(B:O) PAD20.1(P)
N$71: E24.9(C:I0) PAD27.1(P)
N$72: E24.10(C:I1) PAD28.1(P)
N$74: E24.11(C:I2) PAD29.1(P)
N$75: E24.8(C:O) PAD30.1(P)
N$76: E37.9(C:I0) PAD31.1(P)
N$77: E37.10(C:I1) PAD32.1(P)
N$78: E37.8(C:O) PAD33.1(P)
N$79: E37.12(D:I0) PAD34.1(P)
N$80: E37.13(D:I1) PAD35.1(P)
N$81: E37.11(D:O) PAD36.1(P)
N$82: E40.9(B:I0) PAD37.1(P)
N$83: E40.10(B:I1) PAD38.1(P)
N$84: E40.12(B:I2) PAD39.1(P)
N$85: E40.13(B:I3) PAD40.1(P)
N$86: E40.8(B:O) PAD41.1(P)
N$87: E49.12(D:I0) PAD42.1(P)
N$88: E49.13(D:I1) PAD43.1(P)
N$89: E49.11(D:O) PAD44.1(P)
VCC [Power]: U$1.AA2 U$1.BA2 U$1.CA2 U$1.DA2 ; also sheet 1,2,4
Unconnected: U$1.AA1 U$1.AB1 U$1.AJ2 U$1.AR1 U$1.AS1 U$1.AU1 U$1.AV1 U$1.AV2 U$1.BA1 U$1.BB1 U$1.BD2 U$1.BE2 U$1.BH2 U$1.BJ2 U$1.BK2 U$1.BL2 U$1.BM2 U$1.BP2 U$1.BR1 U$1.BR2 U$1.BS1 U$1.BS2 U$1.BU1 U$1.BU2 U$1.BV1 U$1.CA1 U$1.CB1 U$1.CD1 U$1.CD2 U$1.CE1 U$1.CE2 U$1.CH1 U$1.CH2 U$1.CJ1 U$1.CJ2 U$1.CK1 U$1.CK2 U$1.CL1 U$1.CL2 U$1.CM1 U$1.CM2 U$1.CP1 U$1.CP2 U$1.CR1 U$1.CR2 U$1.CS1 U$1.CS2 U$1.CU1 U$1.CU2 U$1.CV1 U$1.CV2 U$1.DA1 U$1.DB1 U$1.DD2 U$1.DE2 U$1.DH2 U$1.DJ2 U$1.DK2 U$1.DL2 U$1.DM2 U$1.DP2 U$1.DR1 U$1.DR2 U$1.DS2 U$1.DU1 U$1.DU2 U$1.DV1 U$1.DV2

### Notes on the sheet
- Unused Gates:
- Omnibus Memory Connectors
- BM812-I-5

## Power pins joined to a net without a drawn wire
GND: E1.7(P:GND) E2.7(P:GND) E3.7(P:GND) E4.7(P:GND) E5.7(P:GND) E6.7(P:GND) E7.7(P:GND) E8.7(P:GND) E9.7(P:GND) E10.7(P:GND) E11.7(P:GND) E12.7(P:GND) E13.7(P:GND) E14.7(P:GND) E15.7(P:GND) E16.7(P:GND) E17.7(P:GND) E18.7(P:GND) E19.7(P:GND) E20.7(P:GND) E21.7(P:GND) E22.7(P:GND) E23.7(P:GND) E24.7(P:GND) E26.7(P:GND) E27.7(P:GND) E28.4(P:GND) E29.4(P:GND) E30.4(P:GND) E31.7(P:GND) E32.4(P:GND) E33.4(P:GND) E34.4(P:GND) E35.7(GND) E36.7(P:GND) E37.7(P:GND) E38.7(GND) E39.7(P:GND) E40.7(P:GND) E41.4(P:GND) E42.4(P:GND) E43.4(P:GND) E44.7(P:GND) E45.4(P:GND) E46.4(P:GND) E47.7(P:GND) E48.7(P:GND) E49.7(P:GND) E50.4(P:GND) E51.4(P:GND) E52.7(P:GND) E53.7(P:GND) IC1.4(GND) IC2.4(GND)
VCC: E1.14(P:VCC) E2.14(P:VCC) E3.14(P:VCC) E4.14(P:VCC) E5.14(P:VCC) E6.14(P:VCC) E7.14(P:VCC) E8.14(P:VCC) E9.14(P:VCC) E10.14(P:VCC) E11.14(P:VCC) E12.14(P:VCC) E13.14(P:VCC) E14.14(P:VCC) E15.14(P:VCC) E16.14(P:VCC) E17.14(P:VCC) E18.14(P:VCC) E19.14(P:VCC) E20.14(P:VCC) E21.14(P:VCC) E22.14(P:VCC) E23.14(P:VCC) E24.14(P:VCC) E26.14(P:VCC) E27.14(P:VCC) E28.8(P:VCC) E29.8(P:VCC) E30.8(P:VCC) E31.14(P:VCC) E32.8(P:VCC) E33.8(P:VCC) E34.8(P:VCC) E35.14(VCC) E36.14(P:VCC) E37.14(P:VCC) E38.14(VCC) E39.14(P:VCC) E40.14(P:VCC) E41.8(P:VCC) E42.8(P:VCC) E43.8(P:VCC) E44.14(P:VCC) E45.8(P:VCC) E46.8(P:VCC) E47.14(P:VCC) E48.14(P:VCC) E49.14(P:VCC) E50.8(P:VCC) E51.8(P:VCC) E52.14(P:VCC) E53.14(P:VCC) IC1.8(VCC) IC2.8(VCC)

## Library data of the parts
C1-C5 = rcl:C-US: CAPACITOR, American symbol
D1-D5 = diode:1N4148: DIODE
E1-E5 E8 E13 E17 E18 E21 E22 E36 E40 E44 E47 E48 = 74xx-jameco:74*20: Dual 4-input NAND gate
E6 E9 E10 E14 E15 E19 E20 E26 E27 E52 E53 = 74xx-jameco:74*74: Dual D type positive edge triggered FLIP FLOP, preset and clear
E7 E16 E24 = 74xx-jameco:74*10: Triple 3-input NAND gate
E11 E23 = 74xx-jameco:74*04: Hex INVERTER
E12 E31 E37 E39 E49 = 74xx-jameco:74*00: Quad 2-input NAND gate
E28-E30 E32-E34 E41-E43 E45 E46 E50 E51 = 74xx-jameco:DS75453: Quad 2-input NAND gate, open collector output
E35 E38 = maxim:MXD1000P: DELAY LINE
H01/H20 H02/H21 H03/H22 H04/H23 H05/H24 = con-lstb:MA17-2: PIN HEADER
IC1 IC2 = maxim:MXD1000: DELAY LINE
JP1 JP3 = jumper:JP2Q: JUMPER
JP2 JP4 = jumper:JP3Q: JUMPER
PAD1-PAD5 PAD12-PAD20 PAD27-PAD44 = wirepad:1,6/0,8: THROUGH-HOLE PAD
R1-R30 = rcl:R-US_: RESISTOR, American symbol
U$1 = dec-con:QUAD: Quad-Height DEC board
U$2 = dec-con:OUTLINE-*: Board outlines for DEC boards.

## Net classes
1 Power: width 0.635 mm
